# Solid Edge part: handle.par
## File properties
Title: Handle
Author: Robert a Rhodes jr
Template: Normal.par
Last saved by: CADCIM
Revision: 11
Application: Solid Edge
Accuracy: 0.99
Material: aluminum
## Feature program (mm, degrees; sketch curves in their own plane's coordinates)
sketch for "unnamed RevolvedProtrusion 1" plane through (0, 0, 0) normal (0, -1, 0) x-axis (1, 0, 0)
  line (-87.868, 0.2971) -> (-87.868, -4)
  line (-87.868, -4) -> (-79.868, -4)
  line (-79.868, -4) -> (-79.868, -5)
  line (-79.868, -5) -> (76.132, -5)
  line (76.132, -5) -> (76.132, -4)
  line (76.132, -4) -> (84.132, -4)
  line (84.132, -4) -> (84.132, 0.2971)
revolve "unnamed RevolvedProtrusion 1" add finite 360 deg about sketch line (-87.868, 0.2971) -> (84.132, 0.2971)
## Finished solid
Body 1: solid body, 7 faces, 6 edges, 0 vertices.
  Faces by surface: plane 4, cylinder 3
  Edges by curve: circle 6
Bounding box of the edges (mm): 172.000 x 10.594 x 10.594, from (-87.868, -5.2971, -5) to (84.132, 5.2971, 5.5941).
Cylindrical faces by radius (mm): R4.2971 x2, R5.2971 x1
Planar faces by outward normal: +x 2, -x 2
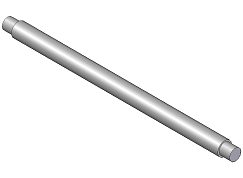
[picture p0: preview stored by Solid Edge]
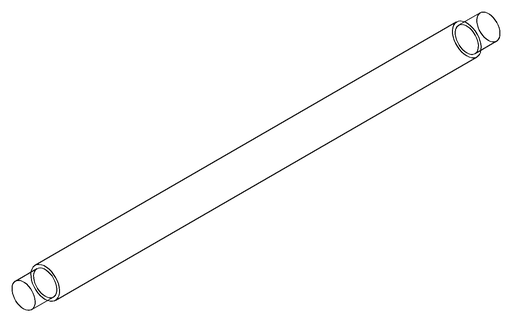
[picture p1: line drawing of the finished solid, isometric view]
